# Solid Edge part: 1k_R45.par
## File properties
Author: Türk
Template: Iso Part.par
Last saved by: Türk
Revision: 16
Application: Solid Edge
Accuracy: 0,990
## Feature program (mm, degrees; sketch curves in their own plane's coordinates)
pattern "PatternOccurrence_1"  XOffset = 6.4286 deg
pattern "PatternOccurrence_5"  XCount = 56; XOffset = 6.4286 deg
pattern "PatternOccurrence_4"  XOffset = 12 deg
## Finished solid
Body 1: solid body, 400 faces, 1190 edges, 792 vertices.
  Faces by surface: plane 227, cylinder 173
  Edges by curve: line 844, circle 346
Bounding box of the edges (mm): 97.899 x 35.000 x 97.899, from (-48.9494, -10, -48.9494) to (48.9494, 25, 48.9494).
Cylindrical faces by radius (mm): R1.25 x30, R14 x1, R15 x30, R45 x56, R49 x56
Planar faces by outward normal: +y 1, -y 2, oblique 224
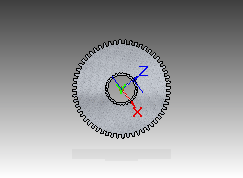
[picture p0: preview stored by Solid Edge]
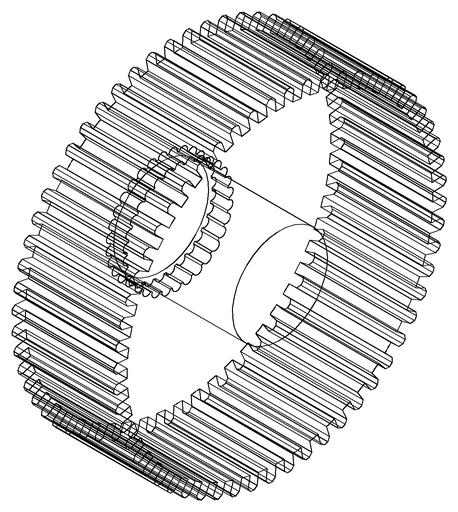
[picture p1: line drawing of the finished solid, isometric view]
